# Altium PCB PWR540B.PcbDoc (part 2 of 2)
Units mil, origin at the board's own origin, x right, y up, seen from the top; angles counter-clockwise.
Board outline 2790 x 2490 mil, 4 copper layers (Top Layer, MidLayer1, MidLayer2, Bottom Layer), stack 95.6 mil thick; 144 components, 56 nets, 352 pads, 322 vias.
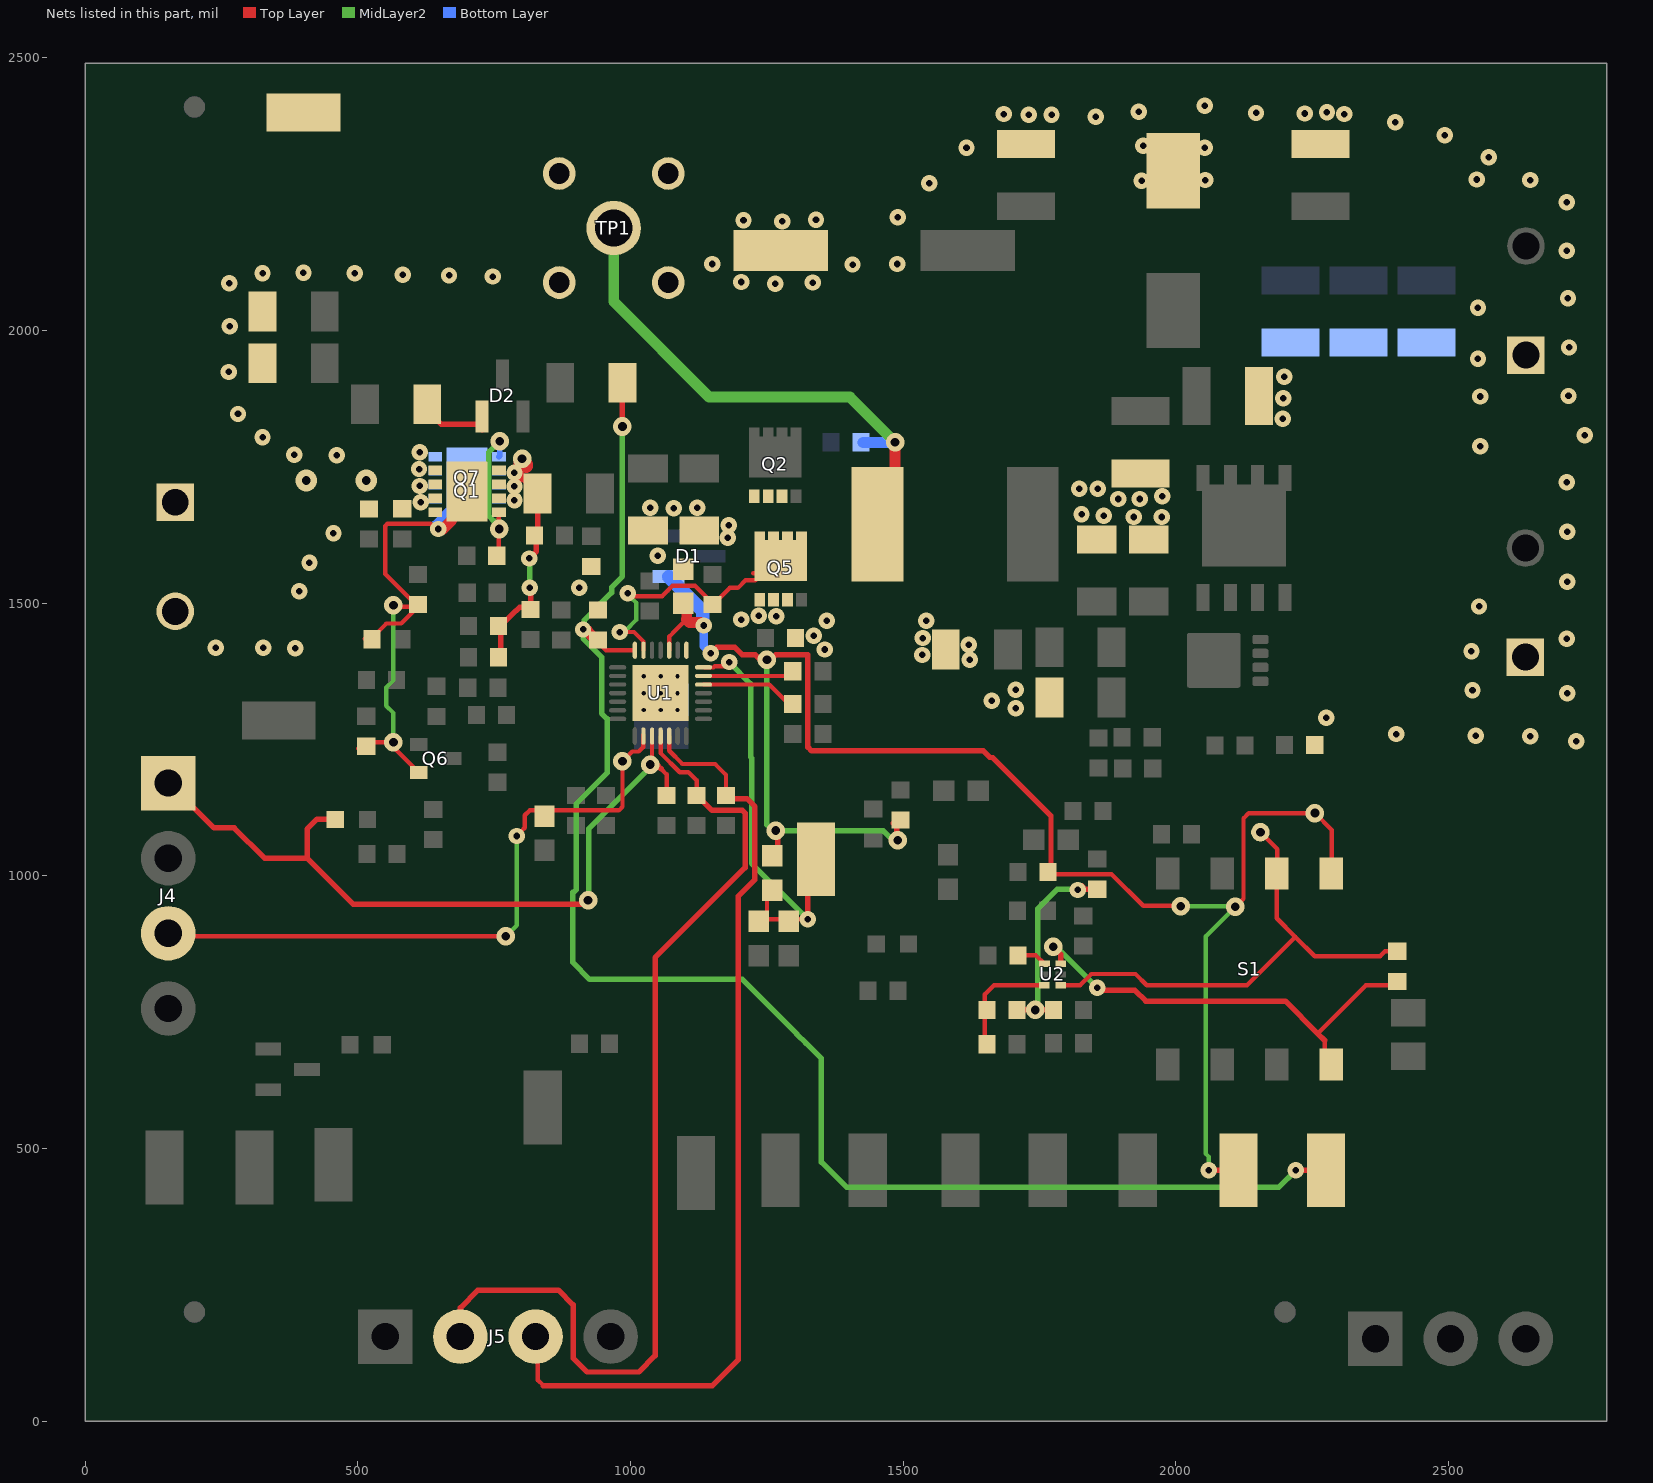
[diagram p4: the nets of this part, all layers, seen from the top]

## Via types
v1: diameter 30, hole 12, Top Layer to Bottom Layer, tented both sides, 239 vias
v2: diameter 34, hole 16, Top Layer to Bottom Layer, tented both sides, 48 vias
v3: diameter 19.68, hole 7.87, Top Layer to Bottom Layer, 15 vias
v4: diameter 28, hole 8, Top Layer to Bottom Layer, tented both sides, 12 vias
v5: diameter 40, hole 16, Top Layer to Bottom Layer, 5 vias
v6: diameter 19.68, hole 7.87, Top Layer to Bottom Layer, tented both sides, 1 vias
v7: diameter 28, hole 10, Top Layer to Bottom Layer, tented both sides, 1 vias
v8: diameter 26, hole 10, Top Layer to Bottom Layer, tented both sides, 1 vias

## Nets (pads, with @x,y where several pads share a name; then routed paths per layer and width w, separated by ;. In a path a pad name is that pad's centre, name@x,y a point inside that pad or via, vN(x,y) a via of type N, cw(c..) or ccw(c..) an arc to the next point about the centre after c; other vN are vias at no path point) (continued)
NetR29_1: R29.1 R31.2 R32.2 | length 402.8
  Top Layer w10: R31.2@1708,755 1709,754 v2(1742,754) R32.2@1775.44,754 R32.2@1776,754 ; v1@1821,974 1823,974 v1@1827,978 ; R29.1@1856,975.44 1829.56,975.44 v1@1827,978 ; v1@1827,978 1829,980 1827,982 1823,982 v1@1827,978
  MidLayer2 w10: v2(1742,754) 1742,762 1747,767 1747,940 1782,975 1821,975 v1@1822,974 ; v1@1821,974 v1@1822,974 ; v1@1822,974 1822.5,973.5 1823,974 v1@1822,974
  other v1: 1820,974
NetR31_1: R31.1 R38.2 U2.3 | length 207.8
  Top Layer w8: R38.2@1649.5,691 1649.5,782.5 1666.32,799.32 U2.3@1758.84,799.32
NetR41_2: R41.2 U2.1 | length 50.7
  Top Layer w8: R41.2@1714.5,854 1743.53,854 U2.1@1758.84,838.69
PHASE27: C15.2 C20.2 L1.1 Q2.1 Q2.2 Q2.3 Q5.5 Q5.6 Q5.7 Q5.8 Q5.9 TP1.1 U1.27 | length 1492.3
  Top Layer w8: v1@980,1446 v1@981,1447 ; v1@980,1448 v1@981,1447 ; v1@982,1446 v1@981,1447 ; v1@998,1513 1058,1513 1068.07,1523.07 1068.07,1523.33 1076.74,1532 1118,1532 1145,1505 1145,1500 1147,1498 1147,1493.35 1181.65,1528 1196.77,1528 1210.77,1542 1228.81,1542 Q5.9@1241.81,1555 ; U1.27@1023.5,1413.74 1023.5,1429.7 1006.1,1447.1 981.1,1447.1 v1@981,1447 ; 1225,1555 Q5.9@1241.81,1555 ; Q5.9@1265,1578.19 Q5.9@1241.81,1555 ; L1.1@1450,1645 L1.1@1485,1680
  Top Layer w20: L1.1@1435,1630 L1.1@1450,1645 ; L1.1@1485,1680 v2(1485,1795)
  MidLayer2 w8: v1@991,1450 1010,1469 1010,1501 1002,1509 v1@1003,1510
  MidLayer2 w20: TP1.1@969,2188 969,2053 1144,1878 1402,1878 v2(1485,1795)
  Bottom Layer w20: C15.2@1426.5,1795 v2(1485,1795)
  other v1: 980,1447 995,1518
PIN21: C32.2 R14.1 R15.1 TP14.1 U1.21 | length 831.2
  Top Layer w8: U1.21@1135,1382 1152,1382 1154,1384 1173,1384 v1(1181,1392) ; R14.1@1260,972 1250,962 1250,920 1321.5,920 v1@1325,916.5 ; R14.1@1274,972 R14.1@1274,975
  Top Layer w10: v1(1325,920) 1325,1015 TP14.1@1340,1030
  MidLayer2 w10: v1@1182,1390 1220,1352 1220,1218 1222,1216 1222,1023 v1(1325,920)
PMON09: J4.3 R34.1 U1.9 | length 1197.4
  Top Layer w8: J4.3@154,896 161,889 v2(771,889) ; v1@787,1082 800,1082 806,1088 806,1111 815,1120 831,1120 978.5,1120 985,1126.5 v2(985,1210) 1003,1228 1015,1228 1023,1236 U1.9@1023,1259
  MidLayer2 w8: v2(771,889) 791,909 v1(791,1073)
PROCHOT10: D4.2 J4.1 R33.1 U1.10 | length 1353.1
  Top Layer w8: v2@1039.25,1208.25 U1.10@1039.25,1256.26 ; 1056,1196 1066,1186 R33.1@1066,1160.12
  Top Layer w10: J4.1@155,1169 236,1088 273,1088 328.8,1032.2 406.8,1032.2 ; D4.2@458,1103 457,1104 425,1104 406.8,1085.8 406.8,1032.2 ; v2@919,948 491,948 406.8,1032.2 ; v2@1036,1205 v2@1039.25,1208.25 ; v2@1048,1204 1056,1196
  MidLayer2 w10: v2@923,955 923,1086 v2@1029,1192
  other v2: 922,955 1036,1204
PWRGND: C1.2 C2.2 C3.2 C4.2 C5.2 C7.2 C8.2 C9.2 C10.2 C11.2 C12.2 C13.2 C21.2 C22.2 C23.2 C26.2 C27.2 C29.2 C30.2 J1.2 J2.1 J3.1 NT1.2 NT2.2 NT3.2 NT4.2 NT5.2 NT6.2 NT7.2 Q5.1 Q5.2 Q5.3 R2.1 R3.1 R11.1 TP1.2 TP1.3 TP1.4 TP1.5 TP3.1 U1.22 U1.29
  other v1: 2734,1247 2650,1256 2550,1257 2404,1260 2276,1290 1706,1307 1662,1321 2718,1335 2544,1340 1706,1341 1622,1396 1535,1405 2542,1412 1356,1415 385,1417 239,1418 326,1418 1620,1424 2717,1435 1536,1436 1336,1440 1360,1468 1542,1468 1203,1470 1267,1476 1235,1477 2556,1494 392,1522 906,1528 2718,1539 411,1574 1050,1587 1178,1620 455,1628 2718,1631 1180,1643 1923,1658 1974,1658 1868,1660 1827,1663 1079,1674 1036,1675 1122,1675 1894,1691 1934,1691 1975,1696 1823,1710 1857,1710 2717,1722 461,1771 383,1772 2558,1788 325,1804 2750,1808 2196,1838 280,1847 2197,1876 2558,1879 2720,1880 2199,1915 263,1924 2554,1948 2721,1969 265,2008 2554,2042 2719,2059 1265,2086 264,2087 1334,2088 1203,2089 747,2099 667,2101 582,2102 325,2105 494,2105 400,2106 1407,2121 1150,2122 1489,2122 2717,2146 1278,2200 1207,2202 1340,2203 1490,2208 2717,2235 1548,2270 1937,2275 2054,2276 2650,2276 2552,2277 2574,2318 1616,2335 2053,2335 1940,2339 2493,2358 2402,2382 1853,2392 1730,2396 1772,2396 1684,2397 2309,2397 2236,2398 2147,2399 2277,2400 1932,2401 2053,2412
  other v3: 1024,1304 1055,1304 1086,1304 1024,1335 1055,1335 1086,1335 1024,1366 1055,1366 1086,1366
Q1_G: Q1.5 Q7.5 R6.2 | length 289.5
  Top Layer w8: R6.2@758.5,1587 Q1.5@758.5,1666.6
  Top Layer w10: Q1.5@758.27,1666.61 758.5,1666.6 Q1.5@758.9,1666.6
  MidLayer2 w10: v2@760,1641 758.9,1641 758.9,1648.9 760,1650 749.9,1650 740,1659.9 740,1776.93 v2(760,1796.93)
  Bottom Layer w10: Q7.5@758.27,1768.39 760,1770.12 v2(760,1796.93)
  other v2: 759,1636
Q1_S: C25.1 Q1.9 Q6.2 Q7.9 R13.2 R46.2 | length 1043
  Top Layer w8: R46.2@500.59,1233.5 515,1233.5 526.5,1245 v2(565,1245) 565,1235.91 Q6.2@611.5,1189.41 ; R13.2@512.5,1435 524.38,1435 552.08,1462.7 579.2,1462.7 C25.1@610,1493.5 ; v2(565,1496) 567.5,1493.5 C25.1@610,1493.5 ; v1@646,1633 633.53,1645.47 554.01,1645.47 550,1641.46 550,1553.5 C25.1@610,1493.5 ; Q1.9@675,1662 675,1680 Q1.9@700,1705
  Top Layer w20: v1@655,1635 Q1.9@671.53,1651.53
  MidLayer2 w8: v2(565,1245) 565,1298.64 552,1311.64 552,1345.36 565,1358.36 565,1495 v2@567,1497
  Bottom Layer w8: v1(647,1636) v1@647,1639 ; 676,1668 Q7.9@676,1694 ; Q7.9@676,1705 Q7.9@683,1712
  Bottom Layer w30: v1@647,1639 676,1668 Q7.9@701,1693
Q1A_D: C6.1 C18.1 D2.1 J1.1 Q1.1 Q1.2 Q1.3 Q1.4 Q7.1 Q7.2 Q7.3 Q7.4 R10.2 | length 88.7
  Top Layer w10: C6.1@646.09,1835 653.09,1828 717.2,1828 D2.1@727.6,1817.6
  other v1: 615,1685 613,1715 612,1746 613,1777
  other v5: 405,1725 515,1725
Q1B_D: C14.1 C16.1 C19.1 Q1.6 Q1.7 Q1.8 Q7.6 Q7.7 Q7.8 R1.1 R8.2 | length 461.5
  Top Layer w10: C19.1@761.5,1401 761.5,1458 790.04,1486.54 791.02,1486.54 797,1492.52 R8.2@816.46,1492.52 ; v1@795,1730 800.39,1730 R1.1@829.37,1701.02 C14.1@829.37,1627.91 ; v1@815,1583 827,1595 827,1620.56 C14.1@830.44,1624 ; v1@816,1530 816.46,1529.54 R8.2@816.46,1492.52 ; R8.2@816.46,1488.58 R8.2@816.46,1492.52
  Top Layer w20: v1@795,1730 795,1763 809,1749 811,1751 811,1755 v2(801,1765)
  MidLayer2 w10: v1(815,1528) v1@815,1581
  other v1: 814,1582 787,1689 787,1714 787,1739
REGN24: C30.1 D1.1 R14.2 R25.1 R26.2 S1.5 TP15.1 U1.24 | length 3266.3
  Top Layer w8: U1.24@1070.75,1413.74 1071,1413.99 1071,1438.84 1076.69,1444.53 1076.69,1444.69 1102.5,1470.5 ; R26.2@1765.5,1003 1882,1003 1940,945 2008,945 v2(2009,944) ; v2(2109,943) 2124,958 2124,1105.23 2133.77,1115 v2(2255,1115) 2286,1084 S1.5@2286,1004.2
  Top Layer w10: v1@1148,1409 1158,1419 1191,1419 1205.02,1404.98 1229,1404.98 1238,1396 v2(1250,1396) 1257,1396 1265.98,1404.98 1325.02,1404.98 1325.02,1235.98 1332,1229 1647,1229 1659,1217 1664,1217 1771,1110 1771,1008.5 R26.2@1765.5,1003 ; v2(1266,1083) 1270,1079 R14.2@1270,1038 ; R25.1@1482,1096 R25.1@1489,1103 ; v2@1488,1070.44 R25.1@1488,1102.44 ; v1(2060,460) TP15.1@2115,460
  Top Layer w20: C30.1@1097,1494 1103,1488 1103,1470.5 ; 1102.5,1470.5 1108.31,1464.69 1128.31,1464.69 v1(1134,1459)
  MidLayer2 w8: v2(2009,944) 2108,944 v2(2109,943) 2055,889 2055,490 2060,485 v1(2060,460)
  MidLayer2 w10: v2(1250,1396) 1250,1094 1261,1083 v2(1266,1083) 1463,1083 v2@1482,1064
  Bottom Layer w15: v1(1134,1459) 1134,1421 v1@1146,1409
  Bottom Layer w25: D1.1@1069.6,1548.6 1132,1486.2 v1@1132,1459
  other v1: 1147,1408
  other v2: 1490,1065
REGN24SW: R28.2 S1.4 U2.6 | length 823.1
  Top Layer w8: 2260,711 2348,799 2398.56,799 R28.2@2406,806.44 ; S1.4@2273,669.8 2273,698
  Top Layer w10: v2(1775,870) 1789.16,855.84 U2.6@1789.16,838.69 ; v1@1855,795 1855,790 1925,790 1945,770 2201,770 2260,711 2273,698
  MidLayer2 w10: v2(1775,870) 1780,870 v1@1855,795
  other v1: 1856,795
S_OUT: pad.0 R28.1 S1.6 U2.4 | length 908.5
  Top Layer w8: U2.4@1789.16,799.32 1824.32,799.32 1845,820 1926,820 1946.68,799.32 2130.32,799.32 2219,888 ; pad.0@2155,1080 2186,1049 2186,977.2 2185,976.2 2185,922 2219,888 ; R28.1@2406,861.56 2383.56,861.56 2374.5,852.5 2254.5,852.5 2219,888
SCL12: J5.3 R35.1 U1.12 | length 1746.5
  Top Layer w8: J5.3@825.59,155 830,150.59 830,75 840,65 ; U1.12@1070.75,1256.26 1070.75,1229.25 1095,1205 1155,1205 1175,1185 1175,1151.5 R35.1@1184.84,1141.65
  Top Layer w10: 840,65 1150,65 1197.5,112.5 1197.5,962.5 1228,993 1228,1127 1213.35,1141.65 R35.1@1184.84,1141.65
SDA11: J5.2 R36.1 U1.11 | length 1865.6
  Top Layer w8: U1.11@1055,1256.26 1055,1225 1090,1190 1106.02,1190 1121,1175.02 R36.1@1121,1148.54
  Top Layer w10: J5.2@687.8,155 687.8,207.8 720,240 867.36,240 894.42,212.94 894.42,115.58 920,90 1015,90 1045,120 1045,850 1210,1015 1210,1115 1205,1120 1149.54,1120 R36.1@1121,1148.54
SRN19: R20.1 U1.19 | length 174.6
  Top Layer w8: U1.19@1133.74,1350.75 1254.25,1350.75 1290,1315 R20.1@1293.52,1315
SRP20: R18.1 U1.20 | length 163.3
  Top Layer w8: U1.20@1133.74,1366.5 1285.02,1366.5 R18.1@1293.52,1375
VCC28: C22.1 R16.1 TP16.1 U1.28 | length 2951.5
  Top Layer w8: C22.1@940,1428.5 954.76,1413.74 U1.28@1007,1413.74
  Top Layer w10: v1@912.74,1457.74 915,1460 915,1455.51 v1@920.7,1449.81 ; v2(985,1824) R16.1@985,1905 ; v1(2220,460) TP16.1@2275,460
  Top Layer w20: v1@920.7,1449.81 920.7,1447.8 C22.1@940,1428.5
  MidLayer2 w10: 894,970.18 894,841 925,810 1205,810 1305,710 1305,709.4 1321.4,693 1322,693 1350,665 1350,475 1396,429 2189,429 v1(2220,460) v1@2225,465 ; 896,970.18 900,974.18 900,1131.82 957,1188.82 957,1288 947,1298 947,1401 912.74,1435.26 v1(912.74,1451.74) 912.74,1457.74 v1@915,1460 ; v1@920.7,1449.81 915,1455.51 v1@915,1460 ; v2(985,1824) 985,1549 965.11,1529.11 965.11,1519.11 915,1469 v1@915,1460
pads on no net: D1.2 FID1.1 FID2.1 FID3.1 FID4.1 FID5.1 FID6.1 Q3.9@2048.74,1356.61 Q3.9@2048.74,1382.2 Q3.9@2048.74,1407.8 Q3.9@2048.74,1433.39 Q3.9@2068.86,1368.92 Q3.9@2068.86,1421.08 Q3.9@2082.11,1395 Q3.9@2103.35,1368.92 Q3.9@2103.35,1421.08

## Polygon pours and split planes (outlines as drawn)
GND on MidLayer2 "MidLayer2-No Net 1" (solid, pour order 61): 40,1374 43.62,1377.62 43.62,1379 955,1379 960,1374 960,1304.98 973.31,1291.68 975.98,1289 1105,1289 1110,1284 1110,1269 1110,1262.31 1120,1252.31 1145,1252.31 1331.69,1252.31 1335,1249 1365,1219 1375,1219 2745,1219 2770,1194 2770,1184 2770,69 2760,59 2685,59 50,59 40,69 40,1374
PWRGND on MidLayer2 "Bottom Layer-No Net 3" (solid, remove dead copper, pour order 60): 38.91,1405.57 38.91,1405.44 52.92,1391.43 85.91,1391.43 963.11,1391.43 969.61,1391.43 977.42,1383.63 977.42,1377.01 977.42,1314.93 990.91,1301.43 1113.91,1301.43 1118.91,1296.43 1123.91,1291.43 1123.91,1271.43 1131.41,1263.93 1336.07,1263.93 1341.43,1258.57 1368.57,1231.43 1369.3,1231.43 2748.91,1231.43 2768.91,1251.43 2768.91,1261.59 2768.91,2441.43 2748.91,2461.43 2725.91,2461.43 48.91,2461.43 38.91,2451.43 38.91,1430.02
PWRGND on Top Layer "Bottom Layer-No Net 3" (solid, remove dead copper, pour order 56): 38.91,1405.57 38.91,1405.44 52.92,1391.43 85.91,1391.43 963.11,1391.43 969.61,1391.43 977.42,1383.63 977.42,1377.01 977.42,1314.93 990.91,1301.43 1113.91,1301.43 1118.91,1296.43 1123.91,1291.43 1123.91,1271.43 1131.41,1263.93 1336.07,1263.93 1341.43,1258.57 1368.57,1231.43 1369.3,1231.43 2748.91,1231.43 2768.91,1251.43 2768.91,1261.59 2768.91,2441.43 2748.91,2461.43 2725.91,2461.43 48.91,2461.43 38.91,2451.43 38.91,1430.02
GND on Top Layer "MidLayer2-No Net 1" (solid, remove dead copper, pour order 57): 40,1375 43.62,1378.62 43.62,1380 955,1380 960,1375 960,1305.98 973.31,1292.68 975.98,1290 1105,1290 1110,1285 1110,1270 1110,1263.31 1120,1253.31 1145,1253.31 1331.69,1253.31 1335,1250 1365,1220 1375,1220 2745,1220 2770,1195 2770,1185 2770,70 2760,60 2685,60 50,60 40,70 40,1375
NetC1_1 on Top Layer "Top Layer-No Net 2" (solid, pour order 48): 910,1745 995,1745 1085,1835 1315,1835 1325,1825 1325,1735 1320,1730 1186.26,1730 1171.26,1715 1171,1715 1160,1711 1016,1711 1010,1705 990,1686.2 976,1672 964,1660 915,1660 915,1660.59 910,1665.59
Q1A_D on Top Layer "Top Layer-No Net 5" (solid, pour order 53): 125.27,1750 551.49,1750 556.62,1750 561.76,1755 572.03,1765 572.03,1880 582.3,1890 664.46,1890 669.59,1890 679.86,1880 685,1875 685,1800 685,1795 679.86,1790 673.44,1783.74 649.05,1783.74 647.76,1783.74 638.78,1775 638.78,1660 633.65,1655 628.51,1660 433.38,1660 356.35,1585 125.27,1585 115,1595 115,1740
Q1B_D on Top Layer "Top Layer-No Net 6" (solid, pour order 46): 750,1750 840,1750 845,1750 855,1740 855,1670 854.41,1670 850,1665.59 849.41,1665 790,1665 770,1685 750,1685
BAT on Top Layer "Top Layer-No Net 9" (solid, pour order 47): 2135,1415 2205,1415 2255,1465 2255,1525 2415,1525 2415,1365 2415,1355 2405,1345 2135,1345
NetC4_1 on Top Layer "Top Layer-No Net 8" (solid, pour order 55): 1535,2195 1555,2195 1625,2265 1905,2265 1945,2225 2055,2225 2065,2225 2115,2275 2315,2275 2317.91,2275 2375,2275 2404,2275 2415,2275 2435,2255 2445,2245 2685,2245 2695,2235 2695,2065 2685,2055 2675,2065 2255,2065 2235,2065 2085,1915 2085,1835 2075,1825 1705,1825 1705,1835 1695,1845 1695,1905 1705,1915 1705,2005 1625,2085 1535,2085 1525,2095 1525,2185
BAT on Top Layer "Top Layer-No Net 7" (solid, pour order 54): 2045,1755.74 2050.46,1765 2394.54,1765 2400,1755.74 2400,1524.26 2394.54,1515 2181.54,1515 2159.42,1515 2128.02,1568.24 2127.74,1568.7 2049.37,1568.7 2049.37,1572.41 2045,1579.81
NetC4_1 on Top Layer "Top Layer-No Net 1" (solid, pour order 51): 1657.84,1776.49 1653.23,1771.52 1653.23,1393 1657.84,1388.02 1667.6,1377.49 1667.96,1377.49 1790.67,1377.49 1791.61,1378.5 1796.23,1383.48 1796.23,1388.02 1796.23,1469.3 1788.16,1478 1787,1478 1787,1771.52 1782.39,1776.49
NetC23_1 on Top Layer "Top Layer-No Net 3" (solid, pour order 52): 1819.57,1545 1819.57,1544.57 1810,1535 1808.74,1533.74 1808.74,1467.48 1808.74,1466.26 1835,1440 1835,1285 1840,1280 1960,1280 1970,1280 2025,1335 2115,1335 2125,1345 2125,1445 2115,1455 2125,1465 2130,1465 2158.62,1465 2165,1471.38 2165,1535 2155,1545 1996.26,1545
NetC4_1 on Top Layer "Top Layer-No Net 4" (solid, pour order 49): 1664,1444 1663,1445 1620,1445 1620,1450 1540,1530 1540,1890 1550,1900 1705,1900 1705,1850 1700,1845 1695,1845 1640,1845 1635,1840 1635,1515 1645,1505 1665,1505
PHASE27 on Top Layer "Top Layer-No Net" (solid, pour order 50): 1205.35,1707.17 1285.35,1707.17 1285.35,1668.24 1294.65,1659.35 1295.35,1659.35 1375.35,1659.35 1385.35,1668.91 1385.35,1745.43 1395.35,1755 1495.35,1755 1505.35,1745.43 1505.35,1544.57 1495.35,1535 1215.35,1535 1205.35,1544.57
GND on MidLayer1 "MidLayer2-No Net 1" (solid, pour order 59): 40,1375 43.62,1378.62 43.62,1380 955,1380 960,1375 960,1305.98 973.31,1292.68 975.98,1290 1105,1290 1110,1285 1110,1270 1110,1263.31 1120,1253.31 1145,1253.31 1331.69,1253.31 1335,1250 1365,1220 1375,1220 2745,1220 2770,1195 2770,1185 2770,70 2760,60 2685,60 50,60 40,70 40,1375
PWRGND on MidLayer1 "Bottom Layer-No Net 3" (solid, pour order 58): 38.91,1405.57 38.91,1405.44 52.92,1391.43 85.91,1391.43 963.11,1391.43 969.61,1391.43 977.42,1383.63 977.42,1377.01 977.42,1314.93 990.91,1301.43 1113.91,1301.43 1118.91,1296.43 1123.91,1291.43 1123.91,1271.43 1131.41,1263.93 1336.07,1263.93 1341.43,1258.57 1368.57,1231.43 1369.3,1231.43 2748.91,1231.43 2768.91,1251.43 2768.91,1261.59 2768.91,2441.43 2748.91,2461.43 2725.91,2461.43 48.91,2461.43 38.91,2451.43 38.91,1430.02
GND on Bottom Layer "MidLayer2-No Net 1" (solid, pour order 67): 40,1375 43.62,1378.62 43.62,1380 955,1380 960,1375 960,1305.98 973.31,1292.68 975.98,1290 1105,1290 1110,1285 1110,1270 1110,1263.31 1120,1253.31 1145,1253.31 1331.69,1253.31 1335,1250 1365,1220 1375,1220 2745,1220 2770,1195 2770,1185 2770,70 2760,60 2685,60 50,60 40,70 40,1375
BAT on Bottom Layer "Bottom Layer-No Net 4" (solid, pour order 65): 2030,1715 2660,1715 2665,1715 2685,1695 2690,1690 2690,1500 2690,1495 2660,1465 2650,1455 2415,1455 2380,1455 2260,1335 2190,1335 2170,1355 2170,1415 2230,1475 2235,1480 2235,1545 2225,1555 2220,1560 2030,1560 2025,1565 2020,1570 2020,1705
NetC4_1 on Bottom Layer "Bottom Layer-No Net" (solid, pour order 64): 2165,2154 2155,2143 2155,2066 2165,2066 2175,2055 2525,2055 2535,2066 2540,2071.5 2540,2159.5 2530,2159.5 2525,2165 2175,2165
Q1A_D on Bottom Layer "Bottom Layer-No Net 1" (solid, pour order 63): 595,1790 600,1795 601.93,1796.93 645,1796.93 648.07,1796.93 650,1795 650,1675 645,1670 600,1670 595,1675
Q1B_D on Bottom Layer "Bottom Layer-No Net 2" (solid, pour order 62): 764,1745 788.06,1768.07 788.06,1770 826.09,1770 829.78,1766.46 835,1761.46 835,1720 835,1710 798.49,1675 779.65,1675 764,1690
PWRGND on Bottom Layer "Bottom Layer-No Net 3" (solid, pour order 66): 38.91,1405.57 38.91,1405.44 52.92,1391.43 85.91,1391.43 963.11,1391.43 969.61,1391.43 977.42,1383.63 977.42,1377.01 977.42,1314.93 990.91,1301.43 1113.91,1301.43 1118.91,1296.43 1123.91,1291.43 1123.91,1271.43 1131.41,1263.93 1336.07,1263.93 1341.43,1258.57 1368.57,1231.43 1369.3,1231.43 2748.91,1231.43 2768.91,1251.43 2768.91,1261.59 2768.91,2441.43 2748.91,2461.43 2725.91,2461.43 48.91,2461.43 38.91,2451.43 38.91,1430.02

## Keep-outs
Keep-Out Layer:
  lines w20: -10,0 ccw(c0,0) 0,-10 ; -10,0 ccw(c0,0) 0,-10 ; -10,0 -10,2490 ; -10,2490 cw(c0,2490) 0,2500 ; -10,2490 cw(c0,2490) 0,2500 ; 0,-10 2790,-10 ; 0,2500 2790,2500 ; 2790,-10 ccw(c2790,0) 2800,0 ; 2790,-10 ccw(c2790,0) 2800,0 ; 2790,2500 cw(c2790,2490) 2800,2490 ; 2790,2500 cw(c2790,2490) 2800,2490 ; 2800,0 2800,2490
  text ".Layer_Name" at 577,-858.49 h60

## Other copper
Top Layer:
  text ".Layer_Name" at 577,-858.49 h60
MidLayer1:
  text ".Layer_Name" at 577,-858.49 h60
MidLayer2:
  text ".Layer_Name" at 577,-858.49 h60
Bottom Layer:
  rectangle net Q1A_D: 130,1650 438,1693
  rectangle net Q1A_D: 130,1669 606,1747
  text ".Layer_Name" at 577,-858.49 h60

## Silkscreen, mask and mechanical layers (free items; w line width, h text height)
Top Overlay:
  text "SYS" at 2283,2082 h45
  text "GND" at 2285,1890 h45
  text "Vin" at 376,1656 h45
  text "BAT" at 2250,1579 h45
  text "GND" at 385,1455 h45
  text "GND" at 2252,1389 h45
  text "PROCHOT" at 273,1147 h40
  text "CMPIN" at 2007,1103 h25 r90
  text "S_OUT" at 2213,1066 h25 r90
  text "CMPOUT" at 2095,1065 h25 r90
  text "REGN" at 2305,1065 h25 r90
  text "GND" at 297,1006 h45
  text "BATPRES" at 1370,915 h25
  text "PMON" at 297,870 h45
  text "ACOK" at 295,734 h45
  text "IADP" at 795,455 h25
  text "CMSRC" at 85,340 h25
  text "ACDRV" at 250,340 h25
  text "ACDET" at 395,340 h25
  text "IBAT" at 1075,340 h25
  text "BATPRES" at 1195,340 h25
  text "Cell" at 1395,340 h25
  text "BAT" at 1570,340 h25
  text "BATDRV" at 1690,340 h25
  text "GND" at 1895,340 h25
  text "REGN" at 2070,340 h25
  text "VCC" at 2240,340 h25
  text "GND" at 580,280 h45 r90
  text "SDA" at 707,278 h45 r90
  text "SCL" at 847,278 h45 r90
  text "3.3V" at 992,278 h45 r90
  text "GND" at 2527,278 h45 r90
  text "CMPIN" at 2657,278 h45 r90
  text "CMPOUT" at 2409,275 h45 r90
  text ".PRJ_Number" at 1305,272 h45
  text ".PCB_Rev" at 1576,272 h45
  text "bq2477xA-540" at 1236,192 h45
  text ".Layer_Name" at 577,-858.49 h60
Bottom Overlay:
  text ".Layer_Name" at 577,-858.49 h60
Top Paste:
  text ".Layer_Name" at 577,-858.49 h60
Bottom Paste:
  text ".Layer_Name" at 577,-858.49 h60
Top Solder:
  text ".Layer_Name" at 577,-858.49 h60
  text ".Layer_Name" at 577,-858.49 h60
Bottom Solder:
  text ".Layer_Name" at 577,-858.49 h60
Drill Guide:
  text ".Layer_Name" at 577,-858.49 h60
M1 Board Outline:
  the board outline again, w10
  text ".Layer_Name" at 577,-858.49 h60
M2 Board Dimensions:
  rectangle: -0.5,-285.5 124.5,-160.5
  rectangle: 124.5,-410.5 499.5,-285.5
  lines w7: -0.5,-285.5 999.5,-285.5 ; 124.5,-410.5 124.5,-160.5 ; 249.5,-410.5 249.5,-160.5 ; 499.5,-410.5 499.5,-160.5 ; 749.5,-410.5 749.5,-160.5 ; -0.5,-410.5 999.5,-410.5 999.5,-160.5 -0.5,-160.5 -0.5,-410.5
  lines w10: -0.5,-475.5 -0.5,-455.5 ; 59.5,-485.5 -0.5,-465.5 ; 59.5,-445.5 -0.5,-465.5 ; 223.58,-465.5 -0.5,-465.5 ; 775.42,-465.5 999.5,-465.5 ; 939.5,-485.5 999.5,-465.5 ; 939.5,-445.5 999.5,-465.5 ; 999.5,-475.5 999.5,-455.5
  text "1000 (mil)" at 233.58,-501.49 h60
  text ".Layer_Name" at 577,-858.49 h60
M3 3D STEP Top:
  text ".Layer_Name" at 577,-858.49 h60
M4 3D STEP Bottom:
  text ".Layer_Name" at 577,-858.49 h60
M5 Assembly Top:
  lines w10: -292,-930.17 6308,-930.17 ; -292,-726.83 6310,-726.83 ; -292,-523.5 -292,-1133.5 3713,-1133.5 6310,-1133.5 6310,-523.5 -291.5,-523.5 -291.5,-1133.5 1284,-1133.5 ; 2173,-1133.5 2173,-523.5 ; 3440,-726.83 3440,-523.5 ; 4280,-726.83 4280,-523.5 ; 4902,-1140 4902,-937.17
  text "COMPONENTS MARKED 'DNP' SHOULD NOT BE POPULATED, AND MAY NOT BE IN BILL OF MATERIALS" at 1153.5,-318.5 h60
  text "ASSEMBLY VARIANT:" at 1153,-434 h60
  text ".VariantName" at 2189,-434 h60
  text "PCB VIEWED FROM TOP SIDE" at -228.5,-655.67 h60
  text "BOARD #:" at 2248,-655.67 h60
  text ".PRJ_Number" at 2793.5,-655.67 h60
  text "REV:" at 3638,-655.67 h60
  text ".PCB_Rev" at 3929.5,-655.67 h60
  text "SVN REV:" at 4476,-655.67 h60
  text ".VersionControl_RevNumber" at 4982,-655.67 h60
  text "IGNORE ->" at -228.5,-858.49 h60
  text "PLOT NAME =" at -228.5,-1064.34 h60
  text ".plot_File_Name" at 577,-1064.34 h60
  text "GENERATED    :" at 2250,-1064.34 h60
  text ".Print_Date" at 3119.5,-1064.34 h60
  text ".Print_Time" at 3848.5,-1064.34 h60
  text "TEXAS INSTRUMENTS" at 5113,-1064.34 h60
M6 Assembly Bottom:
  lines w10: -292.5,-727.33 6309.5,-727.33 ; -290.5,-930.67 6309.5,-930.67 ; 1115.5,-1140.5 1115.5,-937.67 ; 1737.5,-727.33 1737.5,-524 ; 2577.5,-727.33 2577.5,-524 ; 3844.5,-1134 3844.5,-524 ; 4733.5,-1134 6309,-1134 6309,-524 -292.5,-524 -292.5,-1134 2304.5,-1134 6309.5,-1134 6309.5,-524
  text "COMPONENTS MARKED 'DNP' SHOULD NOT BE POPULATED, AND MAY NOT BE IN BILL OF MATERIALS" at 6102,-318 h60
  text ".VariantName" at 5058,-434 h60
  text "ASSEMBLY VARIANT:" at 6097,-434 h60
  text ".VersionControl_RevNumber" at 1035.5,-656.17 h60
  text "SVN REV:" at 1541.5,-656.17 h60
  text ".PCB_Rev" at 2088,-656.17 h60
  text "REV:" at 2379.5,-656.17 h60
  text ".PRJ_Number" at 3224,-656.17 h60
  text "BOARD #:" at 3769.5,-656.17 h60
  text "PCB VIEWED FROM BOTTOM SIDE" at 6246,-656.17 h60
  text "IGNORE ->" at 2547.85,-858.49 h60
  text "TEXAS INSTRUMENTS" at 904.5,-1064.84 h60
  text ".Print_Time" at 2169,-1064.84 h60
  text ".Print_Date" at 2898,-1064.84 h60
  text "GENERATED    :" at 3767.5,-1064.84 h60
  text ".plot_File_Name" at 5440.5,-1064.84 h60
  text "PLOT NAME =" at 6246,-1064.84 h60
M9 Title Sheet:
  drawing of 57 lines, arcs and shapes, not listed
  text "1" at 739.84,8036.5 h70
  text "2" at 3235.5,8036.5 h70
  text "3" at 5724.84,8036.5 h70
  text "4" at 8231.51,8036.5 h70
  text "5" at 10730.5,8036.5 h70
  text "6" at 13235.5,8036.5 h70
  text "A" at -416.5,6893.5 h70
  text "A" at 14383.5,6893.5 h70
  text "B" at -416.5,4513.5 h70
  text "B" at 14383.5,4513.5 h70
  text "C" at -416.5,2138.5 h70
  text "C" at 14383.5,2138.5 h70
  text "PROJECT TITLE:" at 11343.5,277.5 h45
  text ".PRJ_Title" at 11393.5,144.17 h70
  text "DESIGNED FOR:" at 11343.5,-23.5 h45
  text ".PRJ_Customer" at 11393.5,-163.5 h70
  text "D" at -416.5,-231.5 h70
  text "D" at 14383.5,-231.5 h70
  text "FILE NAME:" at 11343.5,-323.5 h45
  text ".PCB_File_Name_No_Path" at 11393.5,-443.5 h70
  text "Texas Instruments (TI) and/or its licensors do not warrant the accuracy or completeness of this specification" at 6374,-605.34 h45
  text "ENGINEER:" at 11343.5,-613.5 h45
  text "LAYOUT BY:" at 12848.5,-613.5 h45
  text "or any information contained therein. TI and/or its licensors do not warrant that this design will meet" at 6329.01,-718 h45
  text ".PRJ_Engineer" at 11393.5,-768.49 h70
  text ".PCB_Layout" at 12899,-768.49 h70
  text "the specifications, will be suitable for your application or fit for any particular purpose, or will operate in" at 6329.01,-830.67 h45
  text ".Layer_Name" at 577,-858.49 h60
  text "ALTIUM DESIGNER VERSION:" at 12848.5,-923.5 h45
  text "an implementation. TI and/or its licensors do not warrant that the design is production worthy. You should" at 6329.01,-943.33 h45
  text "completely validate and test your design implementation to confirm the system functionality for your application." at 6374,-1056 h45
  text ".print_Scale" at 11393.5,-1056.83 h70
  text ".Application_BuildNumber" at 12899,-1056.83 h70
  text "1" at 739.84,-1263.5 h70
  text "2" at 3235.5,-1263.5 h70
  text "3" at 5724.84,-1263.5 h70
  text "4" at 8231.51,-1263.5 h70
  text "5" at 10730.5,-1263.5 h70
  text "6" at 13235.5,-1263.5 h70
M10 Fab Notes:
  drawing of 207 lines, arcs and shapes, not listed
  text "DESIGN INFORMATION" at 12381.02,6810 h60
  text "(REFER ALSO ARRAY/PANEL PROFILING INFORMATION)" at 12019.46,6648.29 h60
  text "BOARD SIZE" at 11333.46,6644 h60
  text "2490mmil" at 11795.78,6516.18 h60
  text "X" at 12301.46,6516.18 h60
  text "2790mil" at 12532.78,6516.18 h60
  text "Number of Layers :" at 11736.46,6319 h60
  text "4" at 12831.27,6309 h60
  text "MIN. TRACK WIDTH:" at 11736.46,6180 h60
  text "8" at 12832.7,6180 h60
  text "MIL" at 12987.46,6180 h60
  text "MIN. CLEARANCE:" at 11736.46,6048 h60
  text "6" at 12832.7,6048 h60
  text "MIL" at 12987.46,6048 h60
  text "MIN. VIA PAD SIZE:" at 11736.46,5916 h60
  text "20" at 12802.71,5916 h60
  text "MIL" at 12987.46,5916 h60
  text "0.05mm (2MIL)" at 12431.46,5774.29 h60
  text "MINIMUM ANNULAR RING" at 11407.23,5770 h60
  text "EXTERNAL" at 13139.46,5770 h60
  text "PER" at 11607.23,5652 h60
  text "IPC-D-275 CLASS 2 LEVEL C" at 11827.23,5652 h60
  text "MIL, HOLES" at 13315.46,5539.71 h60
  text "+/-" at 12923,5539 h60
  text "+/-" at 13777,5539 h60
  text "REGISTRATION TOLERANCES:" at 11407.23,5534 h60
  text "METAL" at 12607,5534 h60
  text "5" at 13183.2,5534 h60
  text "3" at 14016.2,5534 h60
  text "MIL" at 14132.46,5534 h60
  text "MATERIAL:" at 11332.46,5324.54 h60
  text "FR-4 High Tg" at 12318.9,5184.21 h60
  text "FR-4" at 11793.46,5175.64 h60
  text "X" at 12165.46,5175.64 h60
  text "OTHER" at 13241.46,5175.64 h60
  text "31 MIL (0.8mm) +/-10%" at 12073.56,5012.92 h60
  text "THICKNESS:" at 11407.23,5008.64 h60
  text "X" at 11945.4,5008.64 h60
  text "OTHER" at 13358.46,5008.64 h60
  text "TOLERANCE:" at 11407.23,4850.64 h60
  text "X" at 12246.53,4850.64 h60
  text "ANSI IPC-6012 TYPE 3 CLASS 2" at 12433.48,4850.64 h60
  text "OTHER +/-" at 12433.46,4694.64 h60
  text "BOW & TWIST:" at 11407.23,4537.64 h60
  text "X" at 12246.53,4537.64 h60
  text "ANSI IPC-6012 TYPE 3 CLASS 2" at 12433.48,4537.64 h60
  text "OTHER +/-" at 12433.46,4379.13 h60
  text "COPPER THICKNESS (FINISHED):" at 11332.46,4243.64 h60
  text "1.4MIL (1oz)" at 12212.46,4090.92 h60
  text "2MIL (1.4oz)" at 12979.46,4090.92 h60
  text "2.8MIL (2oz)" at 13706.46,4090.92 h60
  text "OUTER:" at 11689.46,4086.64 h60
  text "X" at 12085,4084 h60
  text "1.4MIL (1oz)" at 12212.46,3933.92 h60
  text "2.8MIL (2oz)" at 12979.46,3933.92 h60
  text "N/A" at 13706,3934.29 h60
  text "INNER SIGNAL:" at 11400.38,3929.64 h60
  text "X" at 12085,3928 h60
  text "DRILLING:" at 11332.46,3790.64 h60
  text "REFERENCE:" at 11407.23,3673.64 h60
  text "X" at 12055.46,3673.64 h60
  text "AS SHOWN" at 12242.46,3673.64 h60
  text "X" at 12956.46,3673.64 h60
  text "NC_DRILL FILES" at 13093.46,3673.64 h60
  text "PTH MIN COPPER THICKNESS:" at 11407.23,3515.64 h60
  text "X" at 12757.46,3515.64 h60
  text "1MIL" at 12894.46,3515.64 h60
  text "OTHER" at 13391.46,3515.64 h60
  text "BOARD FINISH:" at 11332.46,3356.64 h60
  text "SILKSCREEN:" at 11487.68,3238.64 h60
  text "X" at 12436.46,3238.64 h60
  text "TOP" at 12562.46,3238.64 h60
  text "X" at 12946.46,3238.64 h60
  text "BOTTOM" at 13073.46,3238.64 h60
  text "SILKSCREEN COLOR:" at 11487.68,3071.64 h60
  text "X" at 12435.42,3071.64 h60
  text "WHITE" at 12562.46,3071.64 h60
  text "OTHER" at 13073.46,3071.64 h60
  text "SOLDER RESIST COLOR:" at 11487.68,2901.64 h60
  text "X" at 12055.42,2742.44 h60
  text "GREEN" at 12182.46,2742.44 h60
  text "BLUE" at 12773.46,2742.44 h60
  text "OTHER" at 13311.46,2742.44 h60
  text "IMMERSION GOLD (ENIG)" at 12393.46,2553.92 h60
  text "SURFACE FINISH:" at 11332.46,2549.64 h60
  text "X" at 12200,2545 h60
  text "IMM. TIN/SILVER OR EQUIV" at 11662,2392.64 h60
  text "OTHER" at 13093.46,2392.64 h60
  text "ARRAY/PANEL:" at 11332.46,2213.64 h60
  text "CUT AND TRIM PER MECH LAYER 1" at 12393.46,2209.35 h60
  text "N.C. ROUTE" at 12393.46,2057.64 h60
  text "X" at 13072.46,2057.64 h60
  text "V. SCORE" at 13259.46,2057.64 h60
  text "CERTIFICATION:" at 11332.46,1920.64 h60
  text "MATERIALS AND WORKMANSHIP FOR ALL PCBS" at 12057.46,1920.64 h60
  text "TO MEET OR EXCEED THE REQUIREMENTS OF:" at 12057.46,1822.64 h60
  text "X" at 11683.96,1686.13 h60
  text "ANSI IPC-A-600F CLASS ->" at 11822.96,1686.13 h60
  text "X" at 13462.02,1686.13 h60
  text "2" at 13580.96,1686.14 h60
  text "1" at 13265.96,1684.64 h60
  text "3" at 13934.96,1684.64 h60
  text "X" at 11686.02,1526.64 h60
  text "UL 94V-0" at 11822.96,1526.64 h60
  text "X" at 12498.02,1526.64 h60
  text "RoHS" at 12634.96,1526.64 h60
  text "OTHER" at 13279.36,1526.64 h60
  text "PER ORDER" at 13676.42,1526.64 h60
  text "ADDITIONAL REQUIREMENTS:" at 11332.46,1385.64 h60
  text "MICROSECTION:" at 11407.23,1270.64 h60
  text "YES" at 12312.96,1270.64 h60
  text "REQUIRED" at 13174.46,1114.49 h60
  text "BARE BOARD ELEC. TEST:" at 11407.23,1111.64 h60
  text "NONE" at 12712.96,1111.64 h60
  text "X" at 13047.46,1111.64 h60
  text "PER ORDER" at 13766.46,1111.64 h60
  text "MANUFACTURER'S ID/LOGO:" at 11407.23,954.64 h60
  text "RAIL" at 12872.96,950.35 h60
  text "X" at 13247.46,950.35 h60
  text "METAL" at 13364.77,950.35 h60
  text "SILK" at 13876.46,950.35 h60
  text ".Layer_Name" at 577,-858.49 h60
M11 Gerber Information:
  lines w10: -292,-930.17 6308,-930.17 ; -292,-726.83 6310,-726.83 ; -292,-523.5 -292,-1133.5 3713,-1133.5 6310,-1133.5 6310,-523.5 -291.5,-523.5 -291.5,-1133.5 1284,-1133.5 ; 2173,-1133.5 2173,-523.5 ; 3440,-726.83 3440,-523.5 ; 4280,-726.83 4280,-523.5 ; 4902,-1140 4902,-937.17
  text "ALL ARTWORK VIEWED FROM TOP SIDE" at -228.5,-655.67 h60
  text "BOARD #:" at 2248,-655.67 h60
  text ".PRJ_Number" at 2793.5,-655.67 h60
  text "REV:" at 3638,-655.67 h60
  text ".PCB_Rev" at 3929.5,-655.67 h60
  text "SVN REV:" at 4476,-655.67 h60
  text ".VersionControl_RevNumber" at 4982,-655.67 h60
  text "LAYER NAME =" at -228.5,-858.49 h60
  text "PLOT NAME =" at -228.5,-1064.34 h60
  text ".plot_File_Name" at 577,-1064.34 h60
  text "GENERATED    :" at 2250,-1064.34 h60
  text ".Print_Date" at 3119.5,-1064.34 h60
  text ".Print_Time" at 3848.5,-1064.34 h60
  text "TEXAS INSTRUMENTS" at 5113,-1064.34 h60
M12 Stackup:
  drawing of 295 lines, arcs and shapes, not listed
  text "Layer" at 6776.74,7793 h60
  text "Name" at 7186.65,7793 h60
  text "Material" at 8116.4,7793 h60
  text "Thickness" at 8976.16,7793 h60
  text "Constant" at 9626,7793 h60
  text "Board Layer Stack" at 10195.86,7793 h60
  text "1" at 6776.74,7673 h60
  text "Top Overlay" at 7186.65,7673 h60
  text "2" at 6776.74,7553 h60
  text "Top Solder" at 7186.65,7553 h60
  text "Solder Resist" at 8116.4,7553 h60
  text "0.40mil" at 8976.16,7553 h60
  text "3.5" at 9626,7553 h60
  text "3" at 6776.74,7433 h60
  text "Top Layer" at 7186.65,7433 h60
  text "Copper" at 8116.4,7433 h60
  text "2.80mil" at 8976.16,7433 h60
  text "4" at 6776.74,7313 h60
  text "Dielectric1" at 7186.65,7313 h60
  text "FR-4" at 8116.4,7313 h60
  text "59.20mil" at 8976.16,7313 h60
  text "4.8" at 9626,7313 h60
  text "5" at 6776.74,7193 h60
  text "MidLayer1" at 7186.65,7193 h60
  text "Copper" at 8116.4,7193 h60
  text "2.80mil" at 8976.16,7193 h60
  text "6" at 6776.74,7073 h60
  text "Dielectric2" at 7186.65,7073 h60
  text "FR-4" at 8116.4,7073 h60
  text "12.60mil" at 8976.16,7073 h60
  text "4.8" at 9626,7073 h60
  text "7" at 6776.74,6953 h60
  text "MidLayer2" at 7186.65,6953 h60
  text "Copper" at 8116.4,6953 h60
  text "2.80mil" at 8976.16,6953 h60
  text "8" at 6776.74,6833 h60
  text "Dielectric3" at 7186.65,6833 h60
  text "FR-4" at 8116.4,6833 h60
  text "12.60mil" at 8976.16,6833 h60
  text "4.8" at 9626,6833 h60
  text "9" at 6776.74,6713 h60
  text "Bottom Layer" at 7186.65,6713 h60
  text "Copper" at 8116.4,6713 h60
  text "2.80mil" at 8976.16,6713 h60
  text "10" at 6776.74,6593 h60
  text "Bottom Solder" at 7186.65,6593 h60
  text "Solder Resist" at 8116.4,6593 h60
  text "0.40mil" at 8976.16,6593 h60
  text "3.5" at 9626,6593 h60
  text "11" at 6776.74,6473 h60
  text "Bottom Overlay" at 7186.65,6473 h60
  text ".Layer_Name" at 577,-858.49 h60
M13 Component Bodies Top:
  text ".Layer_Name" at 577,-858.49 h60
M14 Component Bodies Bottom:
  text ".Layer_Name" at 577,-858.49 h60
M15 Courtyards Top:
  text ".Layer_Name" at 577,-858.49 h60
M16 Courtyards Bottom:
  text ".Layer_Name" at 577,-858.49 h60
Drill Drawing:
  circle w10: c3513.62,1885.83 r20
  circle w10: c3513.62,1885.83 r33.33
  circle w10: c3513.62,1585.83 r33.33
  lines w10: 3480.29,952.5 3480.29,969.17 3496.96,985.83 3480.29,1002.5 3480.29,1019.17 3496.96,1019.17 3513.62,1002.5 3530.29,1019.17 3546.96,1019.17 3546.96,1002.5 3530.29,985.83 3546.96,969.17 3546.96,952.5 3530.29,952.5 3513.62,969.17 3496.96,952.5 3480.29,952.5 ; 3480.29,1102.5 3546.96,1102.5 3546.96,1169.17 3480.29,1169.17 3480.29,1102.5 ; 3480.29,1252.5 3513.62,1269.17 3546.96,1252.5 3530.29,1285.83 3546.96,1319.17 3513.62,1302.5 3480.29,1319.17 3496.96,1285.83 3480.29,1252.5 ; 3480.29,1419.17 3496.96,1419.17 3496.96,1402.5 3530.29,1402.5 3530.29,1419.17 3546.96,1419.17 3546.96,1452.5 3530.29,1452.5 3530.29,1469.17 3496.96,1469.17 3496.96,1452.5 3480.29,1452.5 3480.29,1419.17 ; 3480.29,1719.17 3496.96,1719.17 3513.62,1702.5 3530.29,1719.17 3546.96,1719.17 3530.29,1735.83 3546.96,1752.5 3530.29,1752.5 3513.62,1769.17 3496.96,1752.5 3480.29,1752.5 3496.96,1735.83 3480.29,1719.17 ; 3480.29,2035.83 3513.62,2002.5 3546.96,2035.83 3513.62,2069.17 3480.29,2035.83 ; 3480.29,2152.5 3546.96,2152.5 3546.96,2219.17 3480.29,2219.17 3480.29,2152.5 ; 3493.62,2165.83 3533.62,2165.83 3533.62,2205.83 3493.62,2205.83 3493.62,2165.83
  lines w15: 3420.5,907.5 10540.57,907.5 ; 3420.5,2257.5 10540.57,2257.5 ; 3971.38,757.5 3971.38,2407.5 ; 4571.22,757.5 4571.22,2407.5 ; 5670.9,757.5 5670.9,2407.5 ; 6176.77,757.5 6176.77,2407.5 ; 6910.57,757.5 6910.57,2407.5 ; 8410.13,757.5 8410.13,2407.5 ; 8999.97,757.5 8999.97,2407.5 ; 9745.77,757.5 9745.77,2407.5 ; 3420.5,757.5 10540.57,757.5 10540.57,2407.5 3420.5,2407.5 3420.5,757.5
  text "Symbol" at 3510.5,2302.5 h72
  text "Count" at 4016.38,2302.5 h72
  text "Hole Size" at 4616.22,2302.5 h72
  text "Plated" at 5715.9,2302.5 h72
  text "Hole Type" at 6221.77,2302.5 h72
  text "Drill Layer Pair" at 6955.57,2302.5 h72
  text "Via/Pad" at 8455.13,2302.5 h72
  text "Pad Shape" at 9044.97,2302.5 h72
  text "Template" at 9790.77,2302.5 h72
  text "1" at 4016.38,2152.5 h60
  text "68.00mil (1.727mm)" at 4616.22,2152.5 h60
  text "PTH" at 5715.9,2152.5 h60
  text "Round" at 6221.77,2152.5 h60
  text "Top Layer - Bottom Layer" at 6955.57,2152.5 h60
  text "Pad" at 8455.13,2152.5 h60
  text "Rounded" at 9044.97,2152.5 h60
  text "c254h173" at 9790.77,2152.5 h60
  text "2" at 4016.38,2002.5 h60
  text "10.00mil (0.254mm)" at 4616.22,2002.5 h60
  text "PTH" at 5715.9,2002.5 h60
  text "Round" at 6221.77,2002.5 h60
  text "Top Layer - Bottom Layer" at 6955.57,2002.5 h60
  text "Via" at 8455.13,2002.5 h60
  text "Rounded" at 9044.97,2002.5 h60
  text "(Mixed)" at 9790.77,2002.5 h60
  text "4" at 4016.38,1852.5 h60
  text "38.00mil (0.965mm)" at 4616.22,1852.5 h60
  text "PTH" at 5715.9,1852.5 h60
  text "Round" at 6221.77,1852.5 h60
  text "Top Layer - Bottom Layer" at 6955.57,1852.5 h60
  text "Pad" at 8455.13,1852.5 h60
  text "Rounded" at 9044.97,1852.5 h60
  text "c152h97" at 9790.77,1852.5 h60
  text "6" at 4016.38,1702.5 h60
  text "49.21mil (1.250mm)" at 4616.22,1702.5 h60
  text "PTH" at 5715.9,1702.5 h60
  text "Round" at 6221.77,1702.5 h60
  text "Top Layer - Bottom Layer" at 6955.57,1702.5 h60
  text "Pad" at 8455.13,1702.5 h60
  text "(Mixed)" at 9044.97,1702.5 h60
  text "(Mixed)" at 9790.77,1702.5 h60
  text "11" at 4016.38,1552.5 h60
  text "50.00mil (1.270mm)" at 4616.22,1552.5 h60
  text "PTH" at 5715.9,1552.5 h60
  text "Round" at 6221.77,1552.5 h60
  text "Top Layer - Bottom Layer" at 6955.57,1552.5 h60
  text "Pad" at 8455.13,1552.5 h60
  text "(Mixed)" at 9044.97,1552.5 h60
  text "(Mixed)" at 9790.77,1552.5 h60
  text "12" at 4016.38,1402.5 h60
  text "8.00mil (0.203mm)" at 4616.22,1402.5 h60
  text "PTH" at 5715.9,1402.5 h60
  text "Round" at 6221.77,1402.5 h60
  text "Top Layer - Bottom Layer" at 6955.57,1402.5 h60
  text "Via" at 8455.13,1402.5 h60
  text "Rounded" at 9044.97,1402.5 h60
  text "v71h20m0mx0" at 9790.77,1402.5 h60
  text "16" at 4016.38,1252.5 h60
  text "7.87mil (0.200mm)" at 4616.22,1252.5 h60
  text "PTH" at 5715.9,1252.5 h60
  text "Round" at 6221.77,1252.5 h60
  text "Top Layer - Bottom Layer" at 6955.57,1252.5 h60
  text "Via" at 8455.13,1252.5 h60
  text "Rounded" at 9044.97,1252.5 h60
  text "(Mixed)" at 9790.77,1252.5 h60
  text "54" at 4016.38,1102.5 h60
  text "16.00mil (0.406mm)" at 4616.22,1102.5 h60
  text "PTH" at 5715.9,1102.5 h60
  text "Round" at 6221.77,1102.5 h60
  text "Top Layer - Bottom Layer" at 6955.57,1102.5 h60
  text "(Mixed)" at 8455.13,1102.5 h60
  text "Rounded" at 9044.97,1102.5 h60
  text "(Mixed)" at 9790.77,1102.5 h60
  text "239" at 4016.38,952.5 h60
  text "12.00mil (0.305mm)" at 4616.22,952.5 h60
  text "PTH" at 5715.9,952.5 h60
  text "Round" at 6221.77,952.5 h60
  text "Top Layer - Bottom Layer" at 6955.57,952.5 h60
  text "Via" at 8455.13,952.5 h60
  text "Rounded" at 9044.97,952.5 h60
  text "v76h30m0mx0" at 9790.77,952.5 h60
  text "345 Total" at 4016.38,802.5 h60
  text ".Layer_Name" at 577,-858.49 h60

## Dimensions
0,0 to 0,2490 on M2 Board Dimensions
0,2490 to 2790,2490 on M2 Board Dimensions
